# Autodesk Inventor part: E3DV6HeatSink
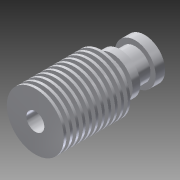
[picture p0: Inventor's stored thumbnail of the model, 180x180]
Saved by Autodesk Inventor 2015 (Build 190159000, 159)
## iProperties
Created: 2014-08
Part Number: E3DV6HeatSink
Material: Aluminum 6061
Document SubType Name: Modeling
Designer: Jack
Density: 2.7 g/cm^3
Appearance: Aluminum - Flat
Author: Jack
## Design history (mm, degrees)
sketch "Sketch1"
  geometry: L1 (0, 0)-(-11.15, 0); L2 (-11.15, 0)-(-11.15, 1); L3 (-11.15, 1)-(0, 1); L4 (0, 1)-(0, 2.5); L5 (0, 2.5)-(-11.15, 2.5); L6 (-11.15, 2.5)-(-11.15, 3.5); L7 (-11.15, 3.5)-(0, 3.5); L8 (0, 3.5)-(0, 5); L9 (0, 5)-(-11.15, 5); L10 (-11.15, 5)-(-11.15, 6); L11 (-11.15, 6)-(0, 6); L12 (0, 6)-(0, 7.5); L13 (0, 7.5)-(-11.15, 7.5); L14 (-11.15, 7.5)-(-11.15, 8.5); L15 (-11.15, 8.5)-(0, 8.5); L16 (0, 8.5)-(0, 10); L17 (0, 10)-(-11.15, 10); L18 (-11.15, 10)-(-11.15, 11); L19 (-11.15, 11)-(0, 11); L20 (0, 11)-(0, 12.5); L21 (0, 12.5)-(-11.15, 12.5); L22 (-11.15, 12.5)-(-11.15, 13.5); L23 (-11.15, 13.5)-(0, 13.5); L24 (0, 13.5)-(0, 15); L25 (0, 15)-(-11.15, 15); L26 (-11.15, 15)-(-11.15, 16); L27 (-11.15, 16)-(0, 16); L28 (0, 16)-(0, 17.5); L29 (0, 17.5)-(-11.15, 17.5); L30 (-11.15, 17.5)-(-11.15, 18.5); L31 (-11.15, 18.5)-(0, 18.5); L32 (0, 18.5)-(0, 20); L33 (0, 20)-(-11.15, 20); L34 (-11.15, 20)-(-11.15, 21); L35 (-11.15, 21)-(0, 21); L36 (0, 21)-(0, 22.5); L37 (0, 22.5)-(-11.15, 22.5); L38 (-11.15, 22.5)-(-11.15, 23.5); L39 (-11.15, 23.5)-(0, 23.5); L40 (0, 23.5)-(0, 25); L41 (0, 25)-(-11.15, 25); L42 (-11.15, 25)-(-11.15, 26); L43 (-11.15, 26)-(0, 26); L44 (0, 26)-(0, 27.5); L45 (0, 27.5)-(-8, 27.5); L46 (-8, 27.5)-(-8, 28.5); L47 (-8, 28.5)-(0, 28.5); L48 (0, 28.5)-(0, 27.5); L49 (0, 26)-(0, 25); L50 (0, 23.5)-(0, 22.5); L51 (0, 21)-(0, 20); L52 (0, 18.5)-(0, 17.5); L53 (0, 16)-(0, 15); L54 (0, 13.5)-(0, 12.5); L55 (0, 11)-(0, 10); L56 (0, 8.5)-(0, 7.5); L57 (0, 6)-(0, 5); L58 (0, 3.5)-(0, 2.5); L59 (0, 1)-(0, 0)
  constraints: 118 end point, 36 point on line, 31 collinear, 28 perpendicular, 10 vertical alignment, 2 vertical, 1 horizontal
  dimensions: "d0" = 11.15 distance of L1.start L1.end; "d1" = 1 distance of L1.end L2.end; "d2" = 1.5 distance of L3.end L4.end; "d3" = 8 distance of L46.end L47.end; "d4" = 1 distance of L45.end L46.end
revolve "Fins" sketch "Sketch1" stored, may be unused: angle "d5" = 90 deg
sketch "Sketch3"
  geometry: L1 (0, 0)-(0, 7); L2 (0, -11.15)-(0, 11.15) reference; L3 (30, 5)-(30, 8); L4 (0, 7)-(30, 5); L5 (28.5, -8)-(28.5, 8) reference; L6 (30, 8)-(33, 8); L7 (33, 8)-(33, 6); L8 (33, 6)-(39, 6); L9 (39, 6)-(39, 8); L10 (39, 8)-(42.7, 8); L11 (42.7, 8)-(42.7, 0); L12 (42.7, 0)-(0, 0)
  constraints: 20 end point, 3 horizontal, 3 perpendicular, 2 vertical, 1 horizontal alignment, 1 point on line
  dimensions: "d20" = 7 distance of L1.start L1.end; "d21" = 8 vertical distance of L1.start L3.end; "d22" = 5 vertical distance of L1.start L3.start; "d23" = 1.5 distance between parallel lines of L5 L3; "d24" = 3 distance of L3.end L6.end; "d25" = 6 vertical distance of L1.start L7.end; "d26" = 6 distance of L7.end L8.end; "d27" = 3.7 distance of L9.end L10.end
revolve "Body" sketch "Sketch3" stored, may be unused: angle "d28" = 90 deg
sketch "Sketch4"
  geometry: C1 r 8 at (0, 0) reference; C2 r 4 at (0, 0)
  constraints: 1 centre point, 1 coincident
  dimensions: "d29" = 8 diameter of C2
extrude "CouplerHole" cut sketch "Sketch4" distance "d30" = 8; taper "d31" = 0 deg
sketch "Sketch5"
  geometry: C1 r 6.433 at (0, 0) reference; C2 r 3.5 at (0, 0)
  constraints: 1 centre point, 1 coincident
  dimensions: "d32" = 7 diameter of C2
extrude "HeadBoltHole" cut sketch "Sketch5" distance "d33" = 10.5; taper "d34" = 0 deg
sketch "Sketch6"
  geometry: C1 r 3.5 at (0, 0) reference; C2 r 2.1 at (0, 0)
  constraints: 1 centre point, 1 coincident
  dimensions: "d35" = 4.2 diameter of C2
extrude "TubeHole" cut sketch "Sketch6" stored distance "d36" = 25.75; taper "d37" = 0 deg
body "Solid1"
